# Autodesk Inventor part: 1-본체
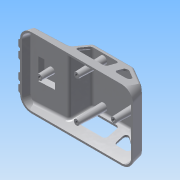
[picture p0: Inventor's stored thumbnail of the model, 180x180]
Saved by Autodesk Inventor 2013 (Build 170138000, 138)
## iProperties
Created: 2015-05
Part Number: 1-본체
Material: ABS 플라스틱
Document SubType Name: Modeling
Designer: Administrator
Density: 7.85 g/cm^3
Mass: 241.072 g
Surface Area: 306.17 cm^2
Volume: 30.7098 cm^3
Author: Administrator
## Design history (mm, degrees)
sketch "스케치1"
  geometry: L1 (-61, 0)-(61, 0); L2 (-61, 0)-(-58.588, 9); L3 (-19, 11.075)-(-13.661, 31); L4 (-13.661, 31)-(31, 31); L5 (31, 31)-(61, 11); L6 (57.412, 13.392)-(61, 0); L7 (-58.588, 9)-(-19, 11.075); L8 (61, 0)-(61, 38); 2 further points
  constraints: 16 end point, 2 point on line, 1 coincident, 1 horizontal, 1 midpoint, 1 parallel, 1 perpendicular
  dimensions: "d0" = 122 distance of L1.start L1.end; "d2" = 105 deg angle of L2 L1; "d5" = 105 deg angle of L1 L6; "d11" = 42 horizontal distance of L3.start L1.start; "d12" = 31 distance between parallel lines of L1 L4; "d13" = 30 horizontal distance of L1.end L4.end; "d14" = 20 vertical distance of L4.end L5.end; "d15" = 9 distance from line of L1 L2.end; "d33" = 3 deg angle of L1 L7
extrude "돌출1" new body sketch "스케치1" stored distance "d16" = 76; taper "d17" = 0 deg
sketch "스케치2"
  geometry: L1 (8.121, 51)-(28.121, 51); L2 (28.121, 51)-(28.121, 25); L3 (28.121, 25)-(8.121, 25); L4 (8.121, 25)-(8.121, 51); L5 (8.121, 51)-(28.121, 25); L6 (28.121, 51)-(8.121, 25); L7 (-2.879, 0)-(-2.879, 76) reference; 3 further points
  constraints: 12 end point, 3 midpoint, 2 parallel, 1 horizontal, 1 horizontal alignment, 1 perpendicular
  dimensions: "d18" = 20 distance of L1.start L1.end; "d20" = 26 distance of L1.end L2.end; "d21" = 11 distance between parallel lines of L4 L7
extrude "돌출2" join sketch "스케치2" distance "d22" = 5; taper "d23" = -20 deg
fillet "모깎기1" dims "d60" = 12
node "작업 평면4"
sketch "스케치7"
  geometry: L1 (0, -38)-(0, -26) reference; L2 (0, 26)-(0, 38) reference; L3 (31, -38)-(23.476, -38) reference; L4 (23.476, 38)-(31, 38) reference; L5 (0, 38)-(31, 29.694); L6 (31, -29.694)-(0, -38); L7 (31, -38)-(31, -29.694); L8 (31, -38)-(0, -38); L9 (31, 29.694)-(31, 38); L10 (0, 38)-(31, 38); 1 further point
  constraints: 12 end point, 3 perpendicular, 1 collinear, 1 point on line
  dimensions: "d62" = 105 deg angle of L2 L5; "d63" = 105 deg angle of L1 L6
extrude "돌출6" cut sketch "스케치7" stored distance "d64" = 5; taper "d65" = 0 deg
feature "쉘1" dims "d24" = 2
sketch "스케치5"
  geometry: L1 (-61, 0)-(61, 0) reference; L2 (57.412, 13.392)-(31, 31) reference; L3 (31, 31)-(-13.661, 31) reference; L4 (-13.661, 31)-(-19, 11.075) reference; L5 (-58.588, 9)-(-61, 0) reference; L6 (29.486, 20.394)-(29.486, 14); L7 (32.486, 11)-(42.078, 11); L8 (43.742, 16.496)-(34.15, 22.891); L9 (-12.832, 14.776)-(-10.42, 23.776); L10 (-7.522, 26)-(17.156, 26); L11 (20.156, 23)-(20.156, 14); L12 (17.156, 11)-(-9.934, 11); A1 r 3 centre (-7.522, 23) between (-7.522, 26) and (-10.42, 23.776); A2 r 3 centre (-9.934, 14) between (-12.832, 14.776) and (-9.934, 11); A3 r 3 centre (17.156, 23) between (20.156, 23) and (17.156, 26); A4 r 3 centre (17.156, 14) between (17.156, 11) and (20.156, 14); A5 r 3 centre (32.486, 20.394) between (34.15, 22.891) and (29.486, 20.394); A6 r 3 centre (32.486, 14) between (29.486, 14) and (32.486, 11); A7 r 3 centre (42.078, 14) between (42.078, 11) and (43.742, 16.496); 6 further points
  constraints: 14 end point, 14 point on circle, 14 tangent, 10 point on line, 7 centre point, 6 equal radius, 5 parallel, 2 perpendicular
  dimensions: "d39" = 15 distance of point (29.486, 26) point (29.486, 11); "d41" = 5 distance from line of point (29.486, 26) L3; "d42" = 5 distance between parallel lines of L8 L2; "d44" = 34 distance of point (20.156, 11) point (-13.844, 11); "d45" = 5 distance between parallel lines of L9 L4; "d46" = 5 distance between parallel lines of L3 L10; "d47" = 15 distance of point (20.156, 26) point (20.156, 11); "d48" = 3 radius of A1
extrude "돌출4" cut sketch "스케치5" stored distance "d49" = 5; taper "d50" = 0 deg
sketch "스케치3"
  geometry: L1 (122, -76)-(122, 0) reference; C1 r 3 at (21, -38); C2 r 3 at (61, -16); C3 r 3 at (61, -60); C4 r 3 at (101, -38); 5 further points
  constraints: 4 centre point, 4 coincident, 3 equal radius, 3 vertical alignment, 2 horizontal alignment
  dimensions: "d25" = 6 diameter of C1; "d27" = 40 horizontal distance of C2.centre C1.centre; "d28" = 40 horizontal distance of C2.centre C4.centre; "d29" = 21 distance from line of L1 C4.centre (derived); "d30" = 6 diameter of C2 (derived); "d31" = 22 distance of C3.centre point (61, -38); "d32" = 22 distance of point (61, -38) C2.centre
extrude "돌출3" join sketch "스케치3" stored distance "d34" = 5; taper "d35" = 2 deg
node "작업 평면1"
sketch "스케치4"
  geometry: 1 further point
node "작업 평면3"
sketch "스케치6"
  geometry: A1 r 4 centre (0, -21) between (0, -25) and (0, -17); A2 r 4 centre (0, -10) between (0, -14) and (0, -6); A3 r 4 centre (0, 10) between (0, 6) and (0, 14); A4 r 4 centre (0, 21) between (0, 17) and (0, 25); 5 further points
  constraints: 8 point on circle, 4 centre point, 3 equal radius, 13 other
  dimensions: "d52" = 8 diameter of A1; "d54" = 11 distance of A2.centre A1.centre; "d55" = 10 distance of point (0, 0) A2.centre; "d56" = 10 distance of point (0, 0) A3.centre; "d57" = 11 distance of A4.centre A3.centre
extrude "돌출5" join sketch "스케치6" stored distance "d58" = 5; taper "d59" = 0 deg
fillet "모깎기2" dims "d66" = 3
fillet "모깎기3" dims "d67" = 3
fillet "모깎기4" dims "d68" = 3
fillet "모깎기5" dims "d69" = 3
fillet "모깎기6" dims "d70" = 3
fillet "모깎기7" dims "d71" = 3
hole "구멍1" sketch "스케치3" diameter "d72" = 3.242; stored, may be unused: countersink angle "d76" = 90 deg, drill point angle "d78" = 118 deg; dims "d73" = 9, "d74" = 4, "d75" = 2, "d77" = 11
chamfer "모따기1" distance "d79" = 1; stored, may be unused: second distance "d80" = 2, angle "d81" = 45 deg
node "솔리드1"
other parameters: "d36" = -3, "d51" = -63, "d61" = 0
